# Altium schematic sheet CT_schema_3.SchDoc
size 287 x 169 mm
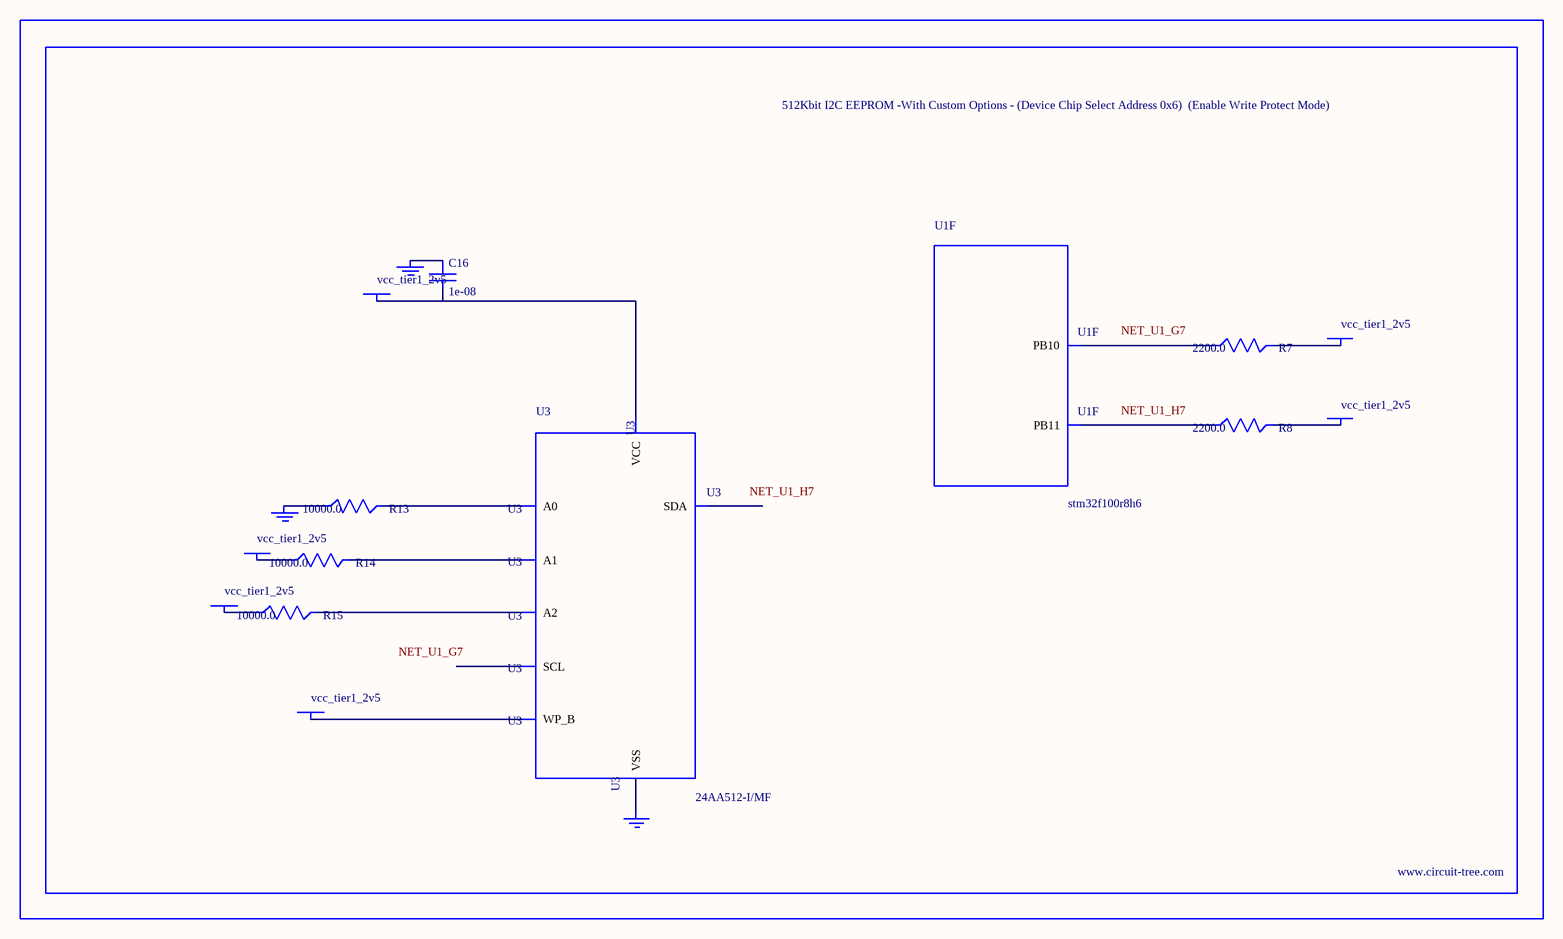
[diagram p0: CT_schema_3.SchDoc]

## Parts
BORDER2  (no value)
C16  1e-08  [C0402]
GND_INSTANCE_2_0  (no value)
GND_INSTANCE_2_1  (no value)
GND_INSTANCE_2_2  (no value)
POWER_INSTANCE_2_0  vcc_tier1_2v5
POWER_INSTANCE_2_1  vcc_tier1_2v5
POWER_INSTANCE_2_2  vcc_tier1_2v5
POWER_INSTANCE_2_3  vcc_tier1_2v5
POWER_INSTANCE_2_4  vcc_tier1_2v5
POWER_INSTANCE_2_5  vcc_tier1_2v5
R7  2200.0  [R0603]
R8  2200.0  [R0603]
R13  10000.0  [R0603]
R14  10000.0  [R0603]
R15  10000.0  [R0603]
U1  stm32f100r8h6  [TFBGA64]  (part F of 7)
U3  24AA512-I/MF  [DFN8-S]

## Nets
NetC16_1: C16.1 GND_INSTANCE_2_1.0(GND)
NetC16_2: C16.2 POWER_INSTANCE_2_3.0(PWR) U3.8(VCC)
NetGND_INSTANCE_2_0_0: GND_INSTANCE_2_0.0(GND) R13.1
NetGND_INSTANCE_2_2_0: GND_INSTANCE_2_2.0(GND) U3.4(VSS)
NetPOWER_INSTANCE_2_0_0: POWER_INSTANCE_2_0.0(PWR) R14.1
NetPOWER_INSTANCE_2_1_0: POWER_INSTANCE_2_1.0(PWR) R15.1
NetPOWER_INSTANCE_2_2_0: POWER_INSTANCE_2_2.0(PWR) U3.7(WP_B)
NetPOWER_INSTANCE_2_4_0: POWER_INSTANCE_2_4.0(PWR) R7.2
NetPOWER_INSTANCE_2_5_0: POWER_INSTANCE_2_5.0(PWR) R8.2
NetR7_1: R7.1 U1.G7(PB10)
NetR8_1: R8.1 U1.H7(PB11)
NetR13_2: R13.2 U3.1(A0)
NetR14_2: R14.2 U3.2(A1)
NetR15_2: R15.2 U3.3(A2)

Not connected (* = marked no-connect by the designer): U3 5(SDA) 6(SCL)

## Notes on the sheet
- Labels drawn without touching a wire or pin: NET_U1_G7, NET_U1_H7

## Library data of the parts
BORDER2 = BORDER_PAGE2
C16 = C0402C103K3RAC
GND_INSTANCE_2_0-GND_INSTANCE_2_2 = GND
POWER_INSTANCE_2_0-POWER_INSTANCE_2_5 = PWR
R7 R8 = RC0603JR-072K2L
R13-R15 = RC0603JR-0710KL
